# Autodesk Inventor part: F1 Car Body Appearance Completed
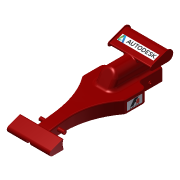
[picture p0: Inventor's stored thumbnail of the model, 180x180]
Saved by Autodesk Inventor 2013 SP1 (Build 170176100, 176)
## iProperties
Created: 2013-01
Part Number: F1 Car Body Appearance Completed
Material: Generic
Document SubType Name: Modeling
Designer: banachd
Density: 0.55 g/cm^3
Mass: 113.444 g
Surface Area: 400.752 cm^2
Volume: 206.262 cm^3
Description: CAR BODY
Author: banachd
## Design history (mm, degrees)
sketch "Sketch1"
  geometry: L1 (0, 0)-(200, 0); L2 (200, 0)-(200, 20); L3 (200, 20)-(110, 20); L4 (0, 8)-(0, 0); A1 r 510.167 centre (110, -490.167) between (110, 20) and (0, 8)
  constraints: 8 end point, 2 perpendicular, 2 point on circle, 1 centre point, 1 horizontal, 1 parallel, 1 tangent
  dimensions: "d0" = 200 distance of L1.start L1.end; "d1" = 20 distance of L1.end L2.end; "d2" = 90 distance of L2.end L3.end; "d3" = 8 distance of L4.start L1.start
extrude "Extrusion1" new body sketch "Sketch1" distance "d4" = 35; taper "d5" = 0 deg
sketch "Sketch2"
  geometry: L1 (0, 0)-(200, 0) reference; L2 (0, 35)-(200, 35) reference; L3 (0, 0)-(0, 35) reference; L4 (0, 10)-(50, 10); L5 (200, 35)-(160, 35); L6 (160, 35)-(160, 19); L7 (160, 19)-(200, 19); L8 (200, 19)-(200, 35); A1 r 120 centre (50, 130) between (50, 10) and (123.314, 35)
  constraints: 10 end point, 3 parallel, 2 point on circle, 2 point on line, 1 centre point, 1 horizontal, 1 perpendicular, 1 tangent
  dimensions: "d6" = 50 distance of L4.start L4.end; "d7" = 40 distance of L7.end L6.end; "d8" = 16 distance of L6.end L5.end; "d9" = 10 distance between parallel lines of L4 L1; "d10" = 120 radius of A1
extrude "Extrusion2" cut sketch "Sketch2" stored distance "d11" = 0; taper "d12" = 0 deg
sketch "Sketch3"
  geometry: L1 (0, 0)-(0, 8) reference; L2 (50, 0)-(0, 0) reference; C1 r 3 at (40, 8)
  constraints: 1 centre point
  dimensions: "d13" = 6 diameter of C1; "d15" = 8 distance from line of C1.centre L2; "d17" = 40 distance from line of C1.centre L1
extrude "Extrusion3" join sketch "Sketch3" distance "d18" = 10; taper "d19" = 0 deg
hole "Hole1" diameter "d22" = 3; stored, may be unused: countersink angle "d26" = 90 deg, drill point angle "d28" = 118 deg; dims "d20" = 10, "d21" = 10, "d23" = 6, "d24" = 4, "d25" = 2, "d27" = 8
pattern_linear "Rectangular Pattern1"
fillet "Fillet1" dims "d32" = 8
mirror "Mirror1"
sketch "Sketch4"
  geometry: L1 (38, 20)-(0, 20) reference; L2 (5, 20)-(5, 30); L3 (33, 30)-(33, 20); L4 (-8, 0)-(-16, 0) reference; A1 r 14 centre (19, 30) between (33, 30) and (5, 30); 2 further points
  constraints: 4 end point, 2 perpendicular, 2 point on circle, 2 point on line, 2 tangent, 1 centre point, 1 midpoint, 1 vertical alignment
  dimensions: "d33" = 30 distance from line of A1.centre L4; "d34" = 14 radius of A1
extrude "Extrusion4" join sketch "Sketch4" distance "d35" = 80; taper "d36" = 0 deg
sketch "Sketch5"
  geometry: L1 (0, 0)-(0, 8) reference; L2 (110, 20)-(120, 20) reference; L3 (120, 20)-(120, 44) reference; L4 (120, 44)-(200, 44) reference; L5 (200, 44)-(200, 0) reference; L6 (200, 0)-(0, 0) reference; L7 (0, 8)-(25.066, 17.123); L8 (168.592, 41)-(193.592, 41); L9 (191.4, 53.43)-(167.908, 44.879); C1 r 1.5 at (180, 8) reference; C2 r 1.5 at (40, 8) reference; A1 r 510.167 centre (110, -490.167) between (110, 20) and (0, 8) reference; A2 r 17.5 centre (40, 8) between (25.066, 17.123) and (24.436, 0); A3 r 6.408 centre (193.592, 47.408) between (193.592, 41) and (191.4, 53.43); A4 r 2 centre (168.592, 43) between (167.908, 44.879) and (168.592, 41)
  constraints: 6 end point, 6 point on circle, 5 tangent, 3 centre point, 1 coincident, 1 parallel, 1 point on line
  dimensions: "d37" = 17.5 radius of A2; "d38" = 25 distance of L8.start L8.end; "d39" = 2 radius of A4; "d40" = 20 deg angle of L8 L9; "d41" = 20 deg angle of L6 L7; "d42" = 3 distance between parallel lines of L8 L4
  node "Project Cut Edges1"
extrude "Extrusion5" join sketch "Sketch5" stored distance "d43" = 70; taper "d44" = 0 deg
extrude "Extrusion6" join sketch "Sketch5" stored distance "d45" = 70; taper "d46" = 0 deg
hole "Hole2" diameter "d49" = 19.5; stored, may be unused: countersink angle "d53" = 90 deg, drill point angle "d55" = 118 deg; dims "d47" = 10, "d48" = 10, "d50" = 6, "d51" = 4, "d52" = 2, "d54" = 55
sketch "Sketch10"
  geometry: L1 (0, 8)-(25.066, 17.123) reference; L2 (110, 20)-(120, 20) reference; L3 (120, 20)-(120, 44) reference; L4 (120, 44)-(166.86, 44) reference; L5 (167.908, 44.879)-(191.4, 53.43) reference; L6 (199.019, 44)-(200, 44) reference; L7 (200, 44)-(200, 39.75) reference; L8 (200, 39.75)-(145, 39.75) reference; L9 (145, 39.75)-(139.142, 30) reference; L10 (139.142, 30)-(145, 20.25) reference; L11 (145, 20.25)-(200, 20.25) reference; L12 (200, 20.25)-(200, 0) reference; L13 (200, 0)-(0, 0) reference; L14 (0, 0)-(0, 8) reference; L15 (120, 20)-(133.856, 44); C1 r 1.5 at (180, 8) reference; C2 r 1.5 at (40, 8) reference; A1 r 17.5 centre (40, 8) between (25.066, 17.123) and (23.1, 12.544) reference; A2 r 510.167 centre (110, -490.167) between (110, 20) and (23.1, 12.544) reference; A3 r 2 centre (168.592, 43) between (167.908, 44.879) and (166.86, 44) reference; A4 r 6.408 centre (193.592, 47.408) between (199.019, 44) and (191.4, 53.43) reference
  constraints: 2 end point, 1 point on line
  dimensions: "d102" = 30 deg angle of L15 L3
extrude "Extrusion8" cut sketch "Sketch10" stored distance "d103" = 10; taper "d104" = 0 deg
sketch "Sketch6"
  geometry: L1 (168.592, 41)-(193.592, 41) reference; L2 (191.4, 53.43)-(167.908, 44.879) reference; L3 (167.224, 46.759)-(190.716, 55.309); L4 (193.592, 39)-(168.592, 39); A1 r 6.408 centre (193.592, 47.408) between (193.592, 41) and (191.4, 53.43) reference; A2 r 2 centre (168.592, 43) between (167.908, 44.879) and (168.592, 41) reference; A3 r 8.408 centre (193.592, 47.408) between (193.592, 39) and (190.716, 55.309); A4 r 4 centre (168.592, 43) between (167.224, 46.759) and (168.592, 39); 1 further point
  constraints: 4 end point, 4 point on circle, 2 centre point, 3 other
  dimensions: "d56" = 2 distance between parallel lines of L3 L2
extrude "Extrusion7" join sketch "Sketch6" distance "d57" = 1; taper "d58" = 0 deg
mirror "Mirror2"
fillet "Fillet2"
fillet "Fillet3" dims "d59" = 2
fillet "Fillet4" dims "d60" = 7
sketch "Sketch7"
  geometry: L1 (25, 68)-(25, 0) reference; L2 (0, 68)-(25, 68) reference; L3 (17.636, 64)-(17.636, 4); L4 (17.636, 4)-(7.364, 4); L5 (7.364, 4)-(7.364, 64); L6 (7.364, 64)-(17.636, 64); 5 further points; 1 other entity
  constraints: 4 midpoint, 1 horizontal alignment, 1 vertical, 1 vertical alignment, 2 other
  dimensions: "d111" = 60 distance of L3.start L3.end
feature "Decal1" sketch "Sketch7"
sketch "Sketch8"
  geometry: L1 (125.993, 18)-(152, 18) reference; L2 (125.993, 0)-(125.993, 18) reference; L3 (126.497, 15.308)-(151.497, 15.308); L4 (151.497, 15.308)-(151.497, 2.692); L5 (151.497, 2.692)-(126.497, 2.692); L6 (126.497, 2.692)-(126.497, 15.308); 5 further points; 1 other entity
  constraints: 4 midpoint, 1 horizontal alignment, 1 vertical alignment, 2 other
  dimensions: "d158" = 25 distance of L4.end L5.end
feature "Decal2" sketch "Sketch8"
sketch "Sketch9"
  geometry: L1 (0, 18)-(26.007, 18) reference; L2 (0, 18)-(0, 0) reference; L3 (0.503, 15.308)-(25.503, 15.308); L4 (25.503, 15.308)-(25.503, 2.692); L5 (25.503, 2.692)-(0.503, 2.692); L6 (0.503, 2.692)-(0.503, 15.308); 5 further points; 1 other entity
  constraints: 4 midpoint, 1 horizontal alignment, 1 vertical alignment, 2 other
  dimensions: "d167" = 25 distance of L4.end L5.end
feature "Decal3" sketch "Sketch9"
sketch "Sketch11"
  geometry: L1 (38, 0)-(0, 0) reference; L2 (16, 6)-(22, 6); L3 (22, 6)-(22, 0); L4 (22, 0)-(16, 0); L5 (16, 0)-(16, 6); 2 further points
  constraints: 8 end point, 2 midpoint, 2 parallel, 1 horizontal, 1 perpendicular
  dimensions: "d105" = 6 distance of L3.end L4.end; "d106" = 6 distance of L2.end L3.end
extrude "Extrusion9" cut sketch "Sketch11" stored distance "d107" = 10; taper "d108" = 0 deg
body "Solid1"
node "Image5"
node "Image8"
node "Image9"
node "Project Cut Edges2"
